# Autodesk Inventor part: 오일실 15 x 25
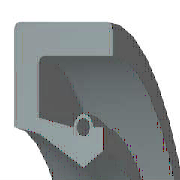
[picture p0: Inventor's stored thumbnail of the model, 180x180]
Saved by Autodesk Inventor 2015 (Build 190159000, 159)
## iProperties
IsCustomPart: 0
Created: 2015-10
Part Number: 오일실 15 x 25
Material: 고무
Description: 오일-실
Document SubType Name: Modeling
Standard: KS B 2804
Designer: mdu
Standards Organization: KS
Language: ko-KR
Size Designation: S - 15 25 7
Categories: <MemberInstance><Categories><Category DisplayName="샤프트 부품" InternalName="7f7aeb1f-a693-4053-b835-cee3144e0d98" Mnemonic="SHFT"><Category DisplayName="실링" Intern
Density: 0.93 g/cm^3
Appearance: 고무 - 검은색 - 버전 1.1
Mass: 1.19654 g
Surface Area: 20.4621 cm^2
Volume: 1.28661 cm^3
Author: mdu
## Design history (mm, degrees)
revolve "본체" stored, may be unused: angle "d17" = 90 deg
revolve "스프링1" stored, may be unused: angle "d18" = 90 deg
body "Solid1"
sketch "스케치1"
  geometry: L1 (0, 12.5)-(7, 12.5); L2 (7, 12.5)-(7, 11.25); L3 (7, 11.25)-(1.75, 11.25); L4 (0, 12.5)-(0, 9.6); L5 (0, 9.6)-(1.75, 9.25); L6 (1.75, 9.25)-(4.9, 7.5); L7 (4.9, 7.5)-(0, 7.5); L8 (6.3, 8.375)-(6.3, 9.6); L9 (0, 0)-(9.586, 0) reference; L10 (4.9, 7.5)-(6.3, 8.375); L11 (0, 18)-(0, -3) reference; L12 (-1.917, 0)-(11.503, 0) reference; L13 (4.2, 9.6)-(1.75, 10.09); L14 (1.75, 10.09)-(1.75, 11.25); L15 (6.3, 9.6)-(5.6, 9.6); C1 r 0.455 at (4.9, 9.6); A1 r 0.7 centre (4.9, 9.6) between (5.6, 9.6) and (4.2, 9.6)
  constraints: 26 end point, 5 horizontal alignment, 4 perpendicular, 2 centre point, 2 collinear, 2 horizontal, 2 parallel, 2 point on circle, 2 point on line, 2 vertical alignment, 1 coincident
  dimensions: "d0" = 25 diameter of L1 L9 (= SD2); "d1" = 16.75 diameter of L8.start L9 (= ABDM); "d2" = 1.25 distance of L1.end L2.end (computed from SD); "d3" = 0.91 diameter of C1 (= SPDI); "d4" = 1.4 diameter of A1 (= SPDA); "d5" = 15 diameter of L6.end L9 (= NND); "d6" = 18.5 diameter of L5.end L9 (= TKDM); "d7" = 19.2 diameter of L4.end L9 (= HLDM); "d8" = 4.9 distance from line of C1.centre L4 (= SPDST); "d9" = 6.3 distance between parallel lines of L8 L4 (= SDI); "d10" = 7 distance between parallel lines of L2 L4 (= SWDT); "d12" = 1.75 distance between parallel lines of L14 L4 (= SD)
fillet "모깎기1" dims "d11" = 0.3 (= RR)
other parameters: "SD2" = 25 [user parameter; used in 1 equation term], "SWDT" = 7 [user parameter; used in 1 equation term], "RR" = 0.3 [user parameter; used in 1 equation term], "SD" = 1.75 [user parameter; used in 2 equation terms], "NND" = 15 [user parameter; used in 1 equation term], "SPDA" = 1.4 [user parameter; used in 1 equation term], "SPDI" = 0.91 [user parameter; used in 1 equation term], "TKDM" = 18.5 [user parameter; used in 1 equation term], "HLDM" = 19.2 [user parameter; used in 1 equation term], "ABDM" = 16.75 [user parameter; used in 1 equation term], "SDI" = 6.3 [user parameter; used in 1 equation term], "SPDST" = 4.9 [user parameter; used in 1 equation term], "d13" = 0, "d14" = 0, "d15" = 0, "LAB" = 0.35 [user parameter]
